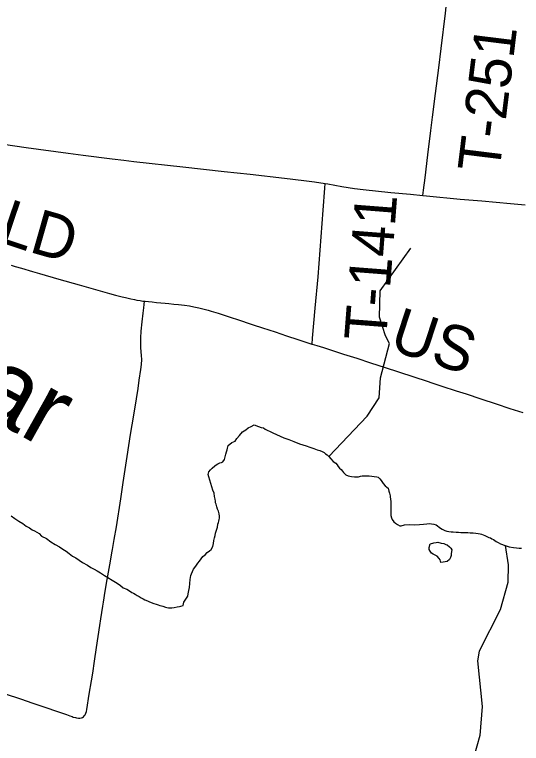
# Model space of a CAD drawing. Extents: x -13.9 to 69.1, y -25.2 to 26.1.
# Drawn here: x 5.08 to 5.691, y 16.946 to 17.826 of the extents above; entities that cross this region are included whole.
import ezdxf

# ---------------------------------------------------------------- set-up
doc = ezdxf.new("R2010")
doc.units = 0
for name, color, linetype in [('GM_X_County_Road', 7, 'Continuous'), ('GM_X_County_Road_Text', 7, 'Continuous'), ('GM_X_Minor_Lake', 7, 'Continuous'), ('GM_X_Minor_River', 7, 'Continuous'), ('GM_X_Minor_River_Text', 7, 'Continuous'), ('GM_X_State_Route', 7, 'Continuous'), ('GM_X_Township_Road', 7, 'Continuous'), ('GM_X_Township_Road_Text', 7, 'Continuous')]:
    doc.layers.add(name, color=color, linetype=linetype)

msp = doc.modelspace()

# ---------------------------------------------------------------- linework, layer by layer
at = {"layer": 'GM_X_County_Road'}
for points in [[(5.07556, 17.52382), (5.08032, 17.52224), (5.08776, 17.51996), (5.10107, 17.51612), (5.10959, 17.51362), (5.13306, 17.50678), (5.15763, 17.49978), (5.1886, 17.49097), (5.19393, 17.48943), (5.20141, 17.4874), (5.2095, 17.48538), (5.21328, 17.48448), (5.21978, 17.48304), (5.22413, 17.48219), (5.22704, 17.4816), (5.23098, 17.48092), (5.23428, 17.48041), (5.23617, 17.48019)], [(5.23617, 17.48019), (5.23712, 17.48007), (5.24112, 17.47977), (5.24552, 17.47927), (5.25102, 17.47871), (5.25597, 17.47821), (5.26147, 17.4777), (5.26587, 17.47729), (5.27193, 17.47672), (5.27742, 17.47616), (5.28454, 17.47536), (5.29054, 17.47451), (5.29597, 17.47357), (5.3019, 17.47232), (5.30834, 17.47074), (5.31313, 17.46939), (5.31685, 17.46829), (5.32533, 17.46562), (5.34224, 17.46014), (5.34751, 17.45837), (5.36759, 17.45178), (5.37869, 17.44813), (5.394, 17.44306), (5.40775, 17.43856), (5.42147, 17.43399), (5.4384, 17.42849), (5.43864, 17.42842)], [(5.43864, 17.42842), (5.44423, 17.42665), (5.45218, 17.42412), (5.46542, 17.4199), (5.47653, 17.41634), (5.49241, 17.41124), (5.50881, 17.40591), (5.52678, 17.40002), (5.54262, 17.39472), (5.56116, 17.38877), (5.57756, 17.38346), (5.58284, 17.38172), (5.59498, 17.37775), (5.61242, 17.37214), (5.62457, 17.36821), (5.64198, 17.36248), (5.66042, 17.35626), (5.67731, 17.35077), (5.69263, 17.34573)]]:
    msp.add_lwpolyline(points, dxfattribs=at)
at = {"layer": 'GM_X_Minor_Lake'}
msp.add_lwpolyline([(5.58127, 17.1872), (5.58534, 17.18861), (5.58838, 17.18893), (5.59041, 17.18927), (5.59445, 17.18813), (5.59748, 17.18773), (5.59983, 17.18661), (5.60151, 17.18586), (5.60419, 17.18365), (5.60587, 17.18217), (5.60719, 17.17998), (5.60647, 17.17562), (5.60645, 17.17307), (5.60541, 17.17091), (5.60438, 17.16837), (5.60131, 17.16586), (5.59658, 17.1652), (5.59388, 17.16486), (5.59289, 17.16778), (5.5919, 17.16961), (5.58956, 17.17219), (5.58688, 17.17368), (5.58453, 17.17479), (5.58251, 17.17591), (5.58119, 17.17847), (5.57985, 17.18031), (5.57988, 17.18285), (5.58094, 17.1872), (5.58127, 17.1872)], dxfattribs=at)
at = {"layer": 'GM_X_Minor_River'}
for points in [[(5.45877, 17.29269), (5.50488, 17.34127), (5.51941, 17.36353), (5.52116, 17.38748), (5.53196, 17.42908), (5.52705, 17.43826), (5.51967, 17.46094), (5.52054, 17.49255), (5.5578, 17.54417)], [(5.25043, 17.11447), (5.25278, 17.11371), (5.2548, 17.11296), (5.25682, 17.11221), (5.2585, 17.11182), (5.26153, 17.1107), (5.26321, 17.11031), (5.26524, 17.10992), (5.26726, 17.1099), (5.26929, 17.10987), (5.27233, 17.1102), (5.27571, 17.11125), (5.27842, 17.11158), (5.28011, 17.11192), (5.28282, 17.11262), (5.28387, 17.11697), (5.28867, 17.12419), (5.28903, 17.12673), (5.28974, 17.13072), (5.29046, 17.13435), (5.29084, 17.13944), (5.29157, 17.14415), (5.29193, 17.14669), (5.29229, 17.14887), (5.29298, 17.15105), (5.29436, 17.15394), (5.2954, 17.15647), (5.29711, 17.15863), (5.29916, 17.16152), (5.30088, 17.16404), (5.30258, 17.1662), (5.30464, 17.16909), (5.30669, 17.17197), (5.30941, 17.17412), (5.3118, 17.17664), (5.31486, 17.17878), (5.3169, 17.18058), (5.31896, 17.18419), (5.31968, 17.18782), (5.32004, 17.19109), (5.32075, 17.19435), (5.32146, 17.19725), (5.32216, 17.20015), (5.32286, 17.20233), (5.32356, 17.20486), (5.32426, 17.2074), (5.32497, 17.21103), (5.32566, 17.21284), (5.32602, 17.21465), (5.32637, 17.21647), (5.32673, 17.21828), (5.32675, 17.22083), (5.32644, 17.22338), (5.32546, 17.22666), (5.32447, 17.22922), (5.32348, 17.23177), (5.32284, 17.23506), (5.32218, 17.23688), (5.3222, 17.2387), (5.32155, 17.24126), (5.32091, 17.24454), (5.32027, 17.24854), (5.31896, 17.2522), (5.31406, 17.26826), (5.31307, 17.27082), (5.31377, 17.27408), (5.31583, 17.2766), (5.31787, 17.27839), (5.32127, 17.28126), (5.32297, 17.2827), (5.32501, 17.28376), (5.32738, 17.28483), (5.32908, 17.28553), (5.33077, 17.28624), (5.33283, 17.28912), (5.33353, 17.29239), (5.33458, 17.29565), (5.33528, 17.29819), (5.33598, 17.30072), (5.33634, 17.3029), (5.33738, 17.3058), (5.3418, 17.30938), (5.34587, 17.31115), (5.34793, 17.3144), (5.351, 17.318), (5.35442, 17.32232), (5.35849, 17.32482), (5.36156, 17.32732), (5.36494, 17.32874), (5.36868, 17.33088), (5.37372, 17.329), (5.37709, 17.32787), (5.37978, 17.32711), (5.38179, 17.32563), (5.38448, 17.3245), (5.38784, 17.32301), (5.3912, 17.32115), (5.39557, 17.31928), (5.39994, 17.31741), (5.40464, 17.31517), (5.41036, 17.31328)], [(5.41036, 17.31328), (5.41641, 17.31066), (5.42348, 17.30803), (5.43156, 17.30575), (5.43593, 17.30388), (5.44064, 17.30237), (5.44467, 17.30087), (5.44803, 17.29973), (5.45072, 17.29861), (5.45308, 17.29749), (5.45475, 17.29601), (5.45676, 17.29453), (5.45877, 17.29269), (5.4611, 17.28976), (5.46377, 17.28645), (5.46713, 17.28459), (5.4688, 17.28275), (5.47012, 17.28055), (5.47179, 17.27872), (5.4738, 17.27687), (5.47513, 17.27504), (5.47647, 17.2732), (5.47914, 17.27063), (5.48216, 17.26913), (5.48621, 17.26836), (5.48958, 17.26832), (5.49262, 17.26828), (5.49465, 17.26826), (5.49701, 17.26896), (5.49904, 17.26929), (5.50748, 17.26919), (5.51052, 17.26879), (5.51355, 17.26839), (5.51658, 17.26799), (5.51827, 17.26761), (5.52027, 17.26576), (5.52194, 17.26356), (5.52427, 17.26026), (5.5266, 17.25732), (5.52861, 17.25548), (5.53029, 17.25437), (5.53093, 17.25072), (5.53192, 17.24853), (5.53256, 17.24525), (5.53288, 17.24343), (5.5332, 17.24161), (5.5335, 17.23796), (5.53347, 17.23469), (5.53344, 17.23142), (5.5334, 17.22742), (5.5337, 17.22414), (5.53368, 17.2216), (5.53432, 17.21868), (5.53532, 17.21649), (5.53732, 17.21392), (5.53932, 17.21207), (5.54167, 17.21059), (5.54436, 17.2091), (5.54604, 17.20908), (5.55011, 17.21012), (5.55551, 17.21042), (5.5626, 17.21034), (5.568, 17.21063), (5.57307, 17.21094), (5.57678, 17.21126), (5.57983, 17.21158), (5.58252, 17.21155), (5.58556, 17.21115), (5.58825, 17.21003), (5.59361, 17.20633), (5.59529, 17.20485), (5.59697, 17.2041), (5.59865, 17.20335), (5.601, 17.2026), (5.6037, 17.2022), (5.6064, 17.20181), (5.60876, 17.20178), (5.61247, 17.20137), (5.61517, 17.20134), (5.61786, 17.20094), (5.62056, 17.20091), (5.6236, 17.20087), (5.6263, 17.20084), (5.62934, 17.20044), (5.63271, 17.2004), (5.63608, 17.19999), (5.63878, 17.1996), (5.64114, 17.1992), (5.64282, 17.19882), (5.64484, 17.19807), (5.64686, 17.19732), (5.64921, 17.1962), (5.6519, 17.19507), (5.65391, 17.19432), (5.65559, 17.19321), (5.65727, 17.19246), (5.65895, 17.19135), (5.66063, 17.19024), (5.66297, 17.18876), (5.666, 17.18727), (5.67138, 17.18502)], [(5.07562, 17.22096), (5.07997, 17.21763), (5.08467, 17.21466), (5.08936, 17.2117), (5.09372, 17.20874), (5.09775, 17.2065), (5.10077, 17.20429), (5.10379, 17.20279), (5.10648, 17.20131), (5.10916, 17.19982), (5.11217, 17.19651), (5.11821, 17.19353), (5.12324, 17.18983), (5.12861, 17.18649), (5.13364, 17.18352), (5.13767, 17.18093), (5.14169, 17.17833), (5.14538, 17.17538), (5.1494, 17.17242), (5.15343, 17.17019), (5.15745, 17.1676), (5.16147, 17.16464), (5.16752, 17.16129), (5.17154, 17.1587), (5.17557, 17.15683), (5.17927, 17.1546), (5.18329, 17.15201), (5.18799, 17.14904), (5.20141, 17.14088), (5.20443, 17.13903), (5.20744, 17.13681), (5.21046, 17.13422), (5.21483, 17.13235), (5.21818, 17.13049), (5.22086, 17.12864), (5.22322, 17.12752), (5.22523, 17.12641), (5.22758, 17.12493), (5.22993, 17.12344), (5.23228, 17.12196), (5.23463, 17.12084), (5.23664, 17.11973), (5.24, 17.11823), (5.24168, 17.11748), (5.24437, 17.11636), (5.24774, 17.11523), (5.25043, 17.11447)], [(5.67138, 17.18502), (5.6752, 17.16199), (5.67485, 17.14055), (5.66554, 17.10766), (5.6401, 17.05763), (5.63823, 17.04603), (5.64371, 16.99067), (5.64078, 16.95583), (5.63361, 16.93016)], [(5.67138, 17.18502), (5.67642, 17.1835), (5.68148, 17.18271), (5.68519, 17.18231), (5.68822, 17.18191), (5.69126, 17.18187)]]:
    msp.add_lwpolyline(points, dxfattribs=at)
at = {"layer": 'GM_X_State_Route'}
msp.add_lwpolyline([(5.06619, 17.66961), (5.0936, 17.66578), (5.14406, 17.65897), (5.16216, 17.65664), (5.19727, 17.65205), (5.21156, 17.65042), (5.22364, 17.64901), (5.28247, 17.6425), (5.3325, 17.63693), (5.36388, 17.63344), (5.40527, 17.6289), (5.42841, 17.62599), (5.44158, 17.62421), (5.45417, 17.62223), (5.45746, 17.62171), (5.47438, 17.61876), (5.48965, 17.6162), (5.50005, 17.61489), (5.5336, 17.61136), (5.55728, 17.60931), (5.57212, 17.60795), (5.57657, 17.60754), (5.61731, 17.60354), (5.64319, 17.60122), (5.67789, 17.59796), (5.69551, 17.59635)], dxfattribs=at)
at = {"layer": 'GM_X_Township_Road'}
for points in [[(5.57212, 17.60795), (5.57293, 17.6144), (5.57479, 17.62913), (5.578, 17.65688), (5.58175, 17.68635), (5.5838, 17.70226), (5.58746, 17.73115), (5.59128, 17.76181), (5.59441, 17.78537), (5.59946, 17.82786), (5.60199, 17.8515), (5.60355, 17.86987), (5.60467, 17.88529), (5.60732, 17.92027), (5.61093, 17.96771), (5.61231, 17.98826)], [(5.43864, 17.42842), (5.43921, 17.4354), (5.44221, 17.47186), (5.44583, 17.5095), (5.4519, 17.58993), (5.45377, 17.61657), (5.45417, 17.62223)], [(5.19712, 17.17651), (5.19778, 17.1803), (5.19985, 17.19258), (5.20244, 17.20774), (5.20764, 17.24173), (5.21062, 17.26109), (5.21554, 17.29268), (5.21954, 17.31907), (5.22329, 17.34251), (5.22657, 17.36242), (5.22856, 17.37472), (5.23008, 17.38468), (5.23189, 17.39759), (5.23265, 17.4036), (5.23297, 17.4097), (5.23261, 17.41478), (5.23203, 17.42368), (5.23177, 17.43021), (5.23192, 17.43615), (5.23251, 17.44385), (5.2336, 17.45507), (5.23481, 17.46566), (5.23542, 17.47215), (5.23617, 17.48019)], [(5.1492, 16.97857), (5.15043, 16.97812), (5.15301, 16.97734), (5.15446, 16.97699), (5.15665, 16.97673), (5.15835, 16.9768), (5.1602, 16.97716), (5.16143, 16.9777), (5.16261, 16.97843), (5.16374, 16.97946), (5.16463, 16.98078), (5.16559, 16.98266), (5.16632, 16.98477), (5.16678, 16.98712), (5.16975, 17.00589), (5.17244, 17.02163), (5.17391, 17.031), (5.17611, 17.04563), (5.17861, 17.06206), (5.18253, 17.08847), (5.18366, 17.0967), (5.18602, 17.11193), (5.18678, 17.11662), (5.18901, 17.13007), (5.19143, 17.14408), (5.19533, 17.16628), (5.19712, 17.17651)], [(5.06843, 17.00618), (5.08685, 17.00001), (5.10158, 16.99495), (5.1137, 16.99089), (5.13368, 16.98391), (5.1421, 16.98102), (5.14633, 16.97962), (5.1492, 16.97857)]]:
    msp.add_lwpolyline(points, dxfattribs=at)

# ---------------------------------------------------------------- texts
at = {"layer": 'GM_X_County_Road_Text'}
for s, height, rotation, p in [('L', 0.05405, 341.51733, (5.05732, 17.55288)), ('D', 0.05414, 344.07834, (5.09566, 17.54012)), ('US', 0.054066, 341.89386, (5.52975, 17.42228))]:
    msp.add_text(s, height=height, rotation=rotation, dxfattribs=at).set_placement(p)
at = {"layer": 'GM_X_Minor_River_Text'}
msp.add_text('Caesar', height=0.089294, rotation=330.74227, dxfattribs=at).set_placement((4.78195, 17.48858))
at = {"layer": 'GM_X_Township_Road_Text'}
for s, height, rotation, p in [('T-251', 0.050614, 82.98692, (5.66432, 17.6343)), ('T-141', 0.050574, 85.57399, (5.52761, 17.43133))]:
    msp.add_text(s, height=height, rotation=rotation, dxfattribs=at).set_placement(p)

doc.saveas('drawing.dxf')
